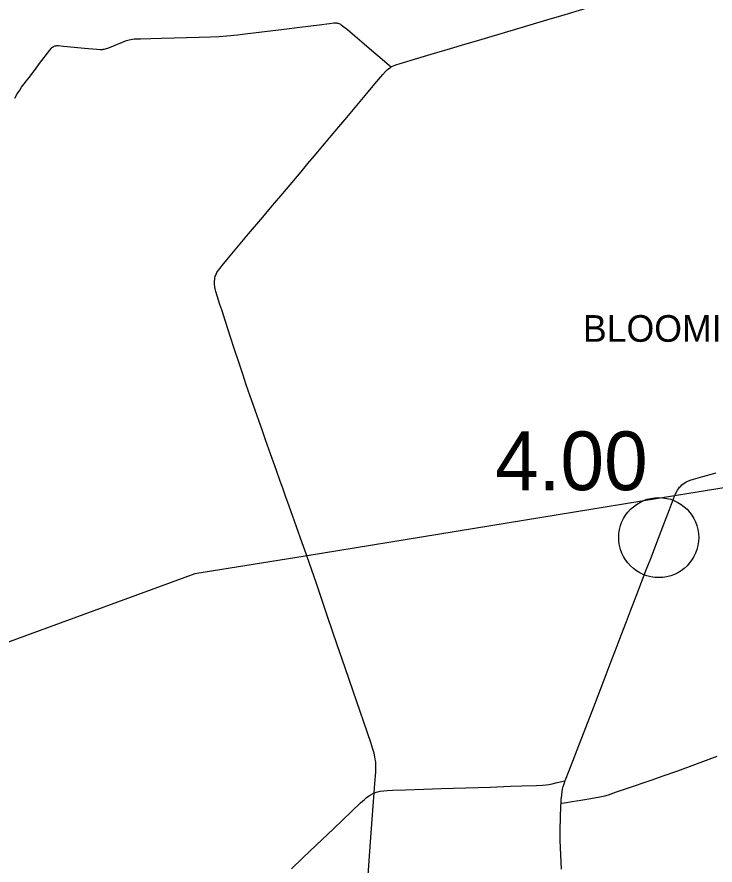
# Model space of a CAD drawing. Extents: x 1597222 to 1925846, y 496284 to 911751.
# Drawn here: x 1697422 to 1710517, y 576766 to 592663 of the extents above; entities that cross this region are included whole.
import ezdxf

# ---------------------------------------------------------------- set-up
doc = ezdxf.new("R2010")
doc.units = 0
for name, color, linetype in [('Default', 7, 'Continuous'), ('GM_X_Corporation_Text', 7, 'Continuous'), ('GM_X_County_Road', 7, 'Continuous'), ('GM_X_State_Route', 7, 'Continuous'), ('GM_X_Township', 7, 'Continuous'), ('GM_X_Township_Road', 7, 'Continuous')]:
    doc.layers.add(name, color=color, linetype=linetype)

msp = doc.modelspace()

# ---------------------------------------------------------------- linework, layer by layer
at = {"layer": 'Default'}
msp.add_circle((1709461, 582905), 750, dxfattribs=at)
msp.add_circle((1709461, 582905), 750, dxfattribs=at)
at = {"layer": 'GM_X_County_Road'}
for points in [[(1704440, 591727), (1704453, 591735), (1704484, 591750), (1704531, 591767), (1704609, 591792), (1704939, 591889), (1705191, 591965), (1705553, 592072), (1705820, 592151), (1706024, 592211), (1706213, 592267), (1706858, 592459), (1707361, 592609), (1707644, 592693), (1708100, 592829), (1708807, 593041), (1709137, 593139), (1709404, 593220), (1709686, 593306), (1710079, 593425), (1710273, 593483), (1710321, 593498)], [(1702859, 582563), (1702845, 582602), (1702775, 582803), (1702561, 583406), (1702505, 583560), (1702458, 583683), (1702407, 583831), (1702361, 583962), (1702291, 584163), (1702181, 584472), (1702087, 584735), (1702026, 584904), (1701860, 585377), (1701791, 585573), (1701761, 585661), (1701717, 585786), (1701664, 585948), (1701584, 586192), (1701498, 586450), (1701430, 586658), (1701333, 586954), (1701263, 587173), (1701230, 587274), (1701176, 587437), (1701152, 587516), (1701140, 587564), (1701131, 587613), (1701129, 587646), (1701127, 587678), (1701128, 587710), (1701131, 587742), (1701136, 587776), (1701143, 587803), (1701152, 587826), (1701159, 587842), (1701173, 587870), (1701185, 587891), (1701202, 587916), (1701231, 587957), (1701271, 588007), (1701387, 588145), (1701610, 588408), (1701768, 588596), (1702033, 588909), (1702181, 589085), (1702254, 589173), (1702408, 589357), (1702750, 589763), (1702877, 589914), (1702994, 590051), (1703289, 590403), (1703458, 590604), (1703607, 590781), (1703733, 590930), (1703986, 591231), (1704134, 591407), (1704283, 591582), (1704338, 591643), (1704373, 591678), (1704399, 591699), (1704426, 591718), (1704440, 591727)], [(1704123, 578119), (1704136, 578292), (1704153, 578505), (1704156, 578587), (1704154, 578652), (1704151, 578701), (1704144, 578749), (1704136, 578797), (1704121, 578861), (1704098, 578940), (1704057, 579064), (1703728, 580026), (1703579, 580461), (1703431, 580896), (1703255, 581408), (1703038, 582044), (1702859, 582563)], [(1704123, 578119), (1704127, 578121), (1704158, 578132), (1704189, 578141), (1704237, 578151), (1704301, 578160), (1704366, 578166), (1704465, 578171), (1704710, 578178), (1705054, 578189), (1705382, 578199), (1705841, 578215), (1706300, 578229), (1706677, 578242), (1706890, 578248), (1707168, 578257), (1707283, 578261), (1707349, 578267), (1707397, 578274), (1707462, 578288), (1707557, 578312), (1707699, 578346), (1707708, 578348)], [(1702574, 576694), (1702787, 576899), (1703036, 577137), (1703357, 577442), (1703865, 577930), (1703938, 577997), (1703975, 578028), (1704014, 578057), (1704055, 578083), (1704098, 578107), (1704123, 578119)], [(1704009, 576575), (1704049, 577115), (1704087, 577622), (1704123, 578119)]]:
    msp.add_lwpolyline(points, dxfattribs=at)
at = {"layer": 'GM_X_State_Route'}
msp.add_lwpolyline([(1707635, 576686), (1707611, 577227), (1707609, 577325), (1707610, 577424), (1707626, 577883), (1707629, 577925), (1707633, 577997), (1707641, 578079), (1707649, 578143), (1707658, 578191), (1707670, 578239), (1707685, 578286), (1707708, 578348), (1707713, 578362), (1707851, 578714), (1707933, 578928), (1708092, 579342), (1708209, 579648), (1708374, 580077), (1708475, 580337), (1708551, 580537), (1708680, 580874), (1708756, 581073), (1708856, 581333), (1708932, 581533), (1709037, 581809), (1709137, 582069), (1709226, 582299), (1709309, 582513), (1709458, 582895), (1709557, 583156), (1709664, 583431), (1709739, 583631), (1709759, 583682), (1709769, 583707), (1709790, 583751), (1709814, 583794), (1709832, 583821), (1709851, 583847), (1709873, 583871), (1709896, 583894), (1709921, 583914), (1709948, 583933), (1709975, 583949), (1710005, 583963), (1710050, 583981), (1710112, 584001), (1710286, 584051), (1710539, 584120)], dxfattribs=at)
at = {"layer": 'GM_X_Township'}
msp.add_lwpolyline([(1720924, 585495), (1719474, 585260), (1716597, 584793), (1709759, 583684), (1702828, 582559), (1700760, 582223), (1696775, 580771)], dxfattribs=at)
at = {"layer": 'GM_X_Township_Road'}
for points in [[(1697381, 591143), (1697428, 591221), (1697473, 591290), (1697510, 591346), (1697649, 591529), (1697748, 591660), (1697847, 591790), (1698036, 592038), (1698067, 592077), (1698078, 592088), (1698091, 592099), (1698105, 592108), (1698119, 592115), (1698135, 592120), (1698151, 592123), (1698167, 592125), (1698200, 592125), (1698298, 592116), (1698494, 592097), (1698690, 592081), (1698919, 592060), (1698985, 592056), (1699008, 592055), (1699024, 592055), (1699042, 592057), (1699059, 592059), (1699082, 592065), (1699098, 592070), (1699129, 592081), (1699265, 592137), (1699402, 592192), (1699479, 592221), (1699526, 592235), (1699558, 592243), (1699590, 592248), (1699623, 592250), (1699738, 592255), (1699935, 592257), (1700132, 592263), (1700837, 592284), (1701050, 592291), (1701214, 592299), (1701361, 592310), (1701557, 592330), (1701704, 592347), (1702013, 592385), (1702436, 592436), (1702730, 592472), (1703088, 592515), (1703283, 592540), (1703365, 592550), (1703397, 592551), (1703414, 592551), (1703430, 592549), (1703446, 592545), (1703461, 592540), (1703477, 592534), (1703491, 592526), (1703505, 592518), (1703531, 592498), (1703620, 592425), (1703758, 592309), (1703932, 592159), (1704071, 592043), (1704271, 591873), (1704407, 591755), (1704440, 591727)], [(1707629, 577925), (1707640, 577927), (1707693, 577933), (1707839, 577957), (1708000, 577984), (1708146, 578007), (1708324, 578036), (1708389, 578049), (1708452, 578066), (1708515, 578085), (1708671, 578137), (1708857, 578200), (1709043, 578265), (1709151, 578302), (1709337, 578366), (1709523, 578430), (1709817, 578535), (1710140, 578653), (1710554, 578809)]]:
    msp.add_lwpolyline(points, dxfattribs=at)

# ---------------------------------------------------------------- texts
at = {"layer": 'Default'}
msp.add_text('4.00', height=1100, dxfattribs=at).set_placement((1706390, 583793))
msp.add_text('4.00', height=1100, dxfattribs=at).set_placement((1706390, 583793))
at = {"layer": 'GM_X_Corporation_Text'}
msp.add_text('BLOOMINGBURG', height=500, rotation=0, dxfattribs=at).set_placement((1708038, 586574))

doc.saveas('drawing.dxf')
